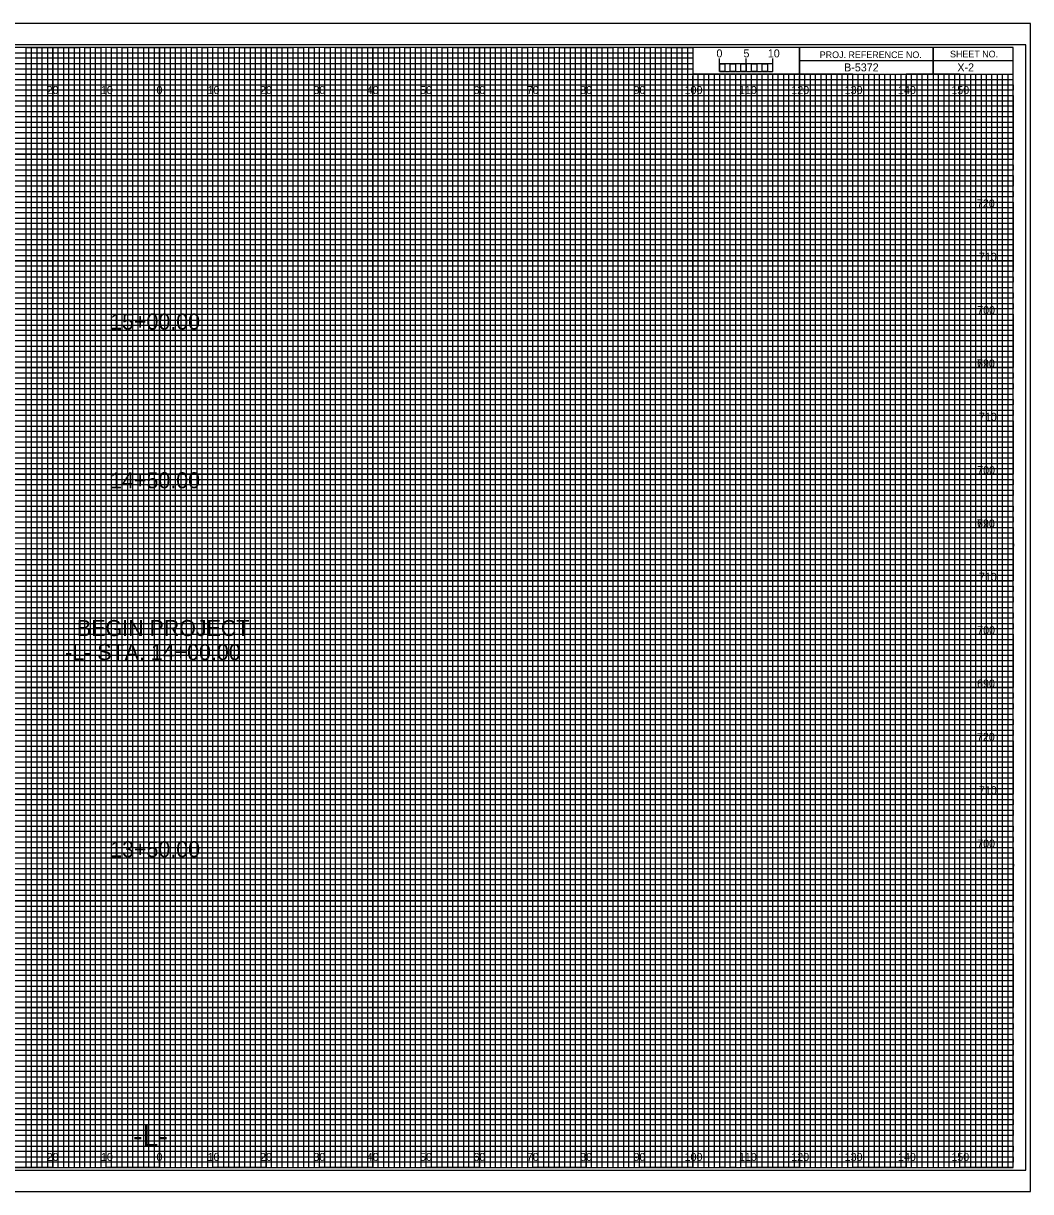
# Model space of a CAD drawing. Extents: x -98 to 717, y -10 to 1974.
# Drawn here: x 134.5 to 323.3, y 215.5 to 434.5 of the extents above; entities that cross this region are included whole.
import ezdxf

# ---------------------------------------------------------------- set-up
doc = ezdxf.new("R2010")
doc.units = 0
for name, color, linetype in [('Exist XS Center Line Elevation Label', 7, 'Continuous'), ('Prop CMT Conc Surface', 7, 'Continuous'), ('Prop CMT Concrete Structures', 7, 'Continuous'), ('Prop CMT Pvmt Course 1', 7, 'Continuous'), ('Prop CMT Pvmt Course 1 CG', 7, 'Continuous'), ('Prop CMT Pvmt Course 2', 7, 'Continuous'), ('Prop CMT Pvmt Course 3', 7, 'Continuous'), ('Prop CMT Pvmt Surface', 7, 'Continuous'), ('Prop CMT Pvmt Surface Shoulder', 7, 'Continuous'), ('Prop CMT Shld Paved Course 1', 7, 'Continuous'), ('Prop CMT Shld Paved Course 2', 7, 'Continuous'), ('Prop CMT Shld Paved Course 3', 7, 'Continuous'), ('Prop CMT Slope Grass', 7, 'Continuous'), ('Prop CMT Subgrade Earthwork', 7, 'Continuous'), ('Prop XS Earthwork Shape', 7, 'Continuous'), ('Prop XS Elevation Labels', 7, 'Continuous'), ('Typical Curb CELL', 7, 'Continuous')]:
    doc.layers.add(name, color=color, linetype=linetype)

msp = doc.modelspace()

# ---------------------------------------------------------------- linework, layer by layer
at = {"layer": 'Exist XS Center Line Elevation Label'}
for p, q in [((0, 429), (260, 429)), ((260, 427.98), (0, 427.98)), ((260, 429), (260, 427.98)), ((0, 427), (260, 427)), ((260, 425.89), (0, 425.89)), ((260, 427), (260, 425.89)), ((0, 424), (320, 424))]:
    msp.add_line(p, q, dxfattribs=at)
for points in [[(0, 423), (270, 423), (320, 423), (320, 422), (0, 422)], [(0, 421), (320, 421), (320, 419), (0, 419)], [(0, 418), (320, 418), (320, 417), (0, 416.98)], [(0, 416), (320, 416), (320, 414), (0, 414)], [(0, 413), (320, 413), (320, 412), (0, 412)], [(0, 411), (320, 411), (320, 409), (0, 409)], [(0, 408), (320, 408), (320, 407), (0, 407)], [(0, 406), (320, 406), (320, 404), (0, 404)], [(0, 403), (320, 403), (320, 402), (0, 402)], [(0, 401), (320, 401), (320, 399), (0, 399)], [(0, 398), (320, 398), (320, 397), (0, 397)], [(0, 396), (320, 396), (320, 393.95), (320, 393), (320, 392), (0, 392)], [(0, 394), (320, 394), (320, 393), (0, 393)], [(0, 391), (320, 391), (320, 389), (0, 389.03)], [(0, 389.03), (320, 389), (320, 388), (0, 388)], [(0, 387), (320, 387), (320, 386), (0, 386)], [(0, 384), (320, 384), (320, 383), (0, 383)], [(0, 382), (320, 382), (320, 381), (0, 381)], [(-0.07, 378.89), (320, 378.89), (320, 377.88), (-0.07, 377.88)], [(0, 377), (320, 377), (320, 376), (0, 376)], [(0, 374), (320, 374), (320, 373), (0, 373)], [(0, 372), (320, 372), (320, 371), (0, 371)], [(0, 369), (320, 369), (320, 368), (0, 368)], [(0, 367), (320, 367), (320, 366), (0, 366)], [(0, 364), (320, 364), (320, 363), (0, 363)], [(0, 362), (320, 362), (320, 361), (0, 361)], [(0, 359), (320, 359), (319.99, 357.98), (0, 358)], [(0, 357), (320, 357), (320, 356), (0, 356)], [(0, 354), (320, 354), (320, 353), (0, 353)], [(0, 352), (320, 352), (320, 351), (0, 351)], [(0, 349), (320, 349), (320, 348), (0, 348)], [(0, 347), (320, 347), (320, 346), (0, 346)], [(0, 344), (320, 344), (320, 343), (0, 343)], [(0, 342), (320, 342), (320, 341), (0, 341)], [(0, 339), (320, 339), (320, 338), (0, 338)], [(0, 336.99), (320.07, 336.91), (320, 336), (0, 336)], [(0, 334), (320, 334), (320, 333), (0, 333)], [(0, 332), (320, 332), (320, 331), (0, 331)], [(0, 329), (320, 329), (320, 328), (0, 328)], [(0, 327), (320, 327), (320, 326), (0, 326)], [(0, 324), (320, 324), (320, 323), (0, 323)], [(0, 322), (320, 322), (320, 321), (0, 321)], [(0, 319), (320, 319), (320, 318), (0, 318)], [(0, 317), (320, 317), (320, 316), (0, 316)], [(0, 314), (320, 314), (320, 313), (0, 313)], [(0, 312), (320, 312), (320, 311), (0, 311)], [(0, 309), (320, 309), (320, 308), (0, 308)], [(0, 307), (320, 307), (320, 306), (0, 306)], [(0, 304), (320, 304), (320, 303), (0, 303)], [(0, 302), (320, 302), (320, 301), (0, 301)], [(0, 299), (320, 299), (319.99, 297.98), (0, 298)], [(0, 297), (320, 297), (320, 296), (0, 296)], [(0, 294), (320, 294), (320, 293), (0, 293)], [(0, 292), (320, 292), (320, 291), (0, 291)], [(0, 289), (320, 289), (320, 288), (0, 288)], [(0, 287), (320, 287), (320, 286), (0, 286)], [(0, 284), (320, 284), (320, 283), (0, 283)], [(0, 282), (320, 282), (320, 281), (0, 281)], [(0, 279), (320, 279), (320, 278), (0, 278)], [(0, 276.99), (320.07, 276.91), (320, 276), (0, 276)], [(0, 274), (320, 274), (320, 273), (0, 273)], [(0, 272), (320, 272), (320, 271), (0, 271)], [(0, 269), (320, 269), (320, 268), (0, 268)], [(0, 267), (320, 267), (320, 266), (0, 266)], [(0, 264), (320, 264), (320, 263), (0, 263)], [(0, 262), (320, 262), (320, 261), (0, 261)], [(0, 259), (320, 259), (320, 258), (0, 258)], [(0, 257), (320, 257), (320, 256), (0, 256)], [(0, 254), (320, 254), (320, 253), (0, 253)], [(0, 252), (320, 252), (320, 251), (0, 251)], [(0, 249), (320, 249), (320, 248), (0, 248)], [(0, 247), (320, 247), (320, 246), (0, 246)], [(0, 244), (320, 244), (320, 243), (0, 243)], [(0, 242), (320, 242), (320, 241), (0, 241)], [(0, 239), (320, 239), (320, 238), (0, 238)], [(0, 237), (320, 237), (320, 236), (0, 236)], [(0, 234), (320, 234), (320, 233), (0, 233)], [(0, 232), (320, 232), (320, 231), (0, 231)], [(0, 229), (320, 229), (320, 228), (0, 228)], [(0, 227), (320, 227), (320, 226), (0, 226)], [(0, 224), (320, 224), (320, 223), (0, 223)], [(0, 222), (320, 222), (320, 221), (0, 221)]]:
    msp.add_lwpolyline(points, dxfattribs=at)
at = {"layer": 'Prop CMT Conc Surface'}
for p, q in [((305, 430), (305, 425)), ((305, 425), (305, 430)), ((280, 427.5), (280, 425)), ((320, 427.49), (280, 427.49)), ((280, 425), (320, 425))]:
    msp.add_line(p, q, dxfattribs=at)
for points in [[(320, 430), (0, 430), (0, 220), (320, 220)], [(280, 430), (260, 430), (260, 425.03), (280, 425.03)], [(320, 430), (280, 430), (280, 425), (320, 425)]]:
    msp.add_lwpolyline(points, close=True, dxfattribs=at)
at = {"layer": 'Prop CMT Concrete Structures'}
for p, q in [((140, 220), (140, 430)), ((150, 220), (150, 430)), ((160, 220), (160, 430)), ((170, 220), (170, 430)), ((180, 220), (180, 430)), ((190, 220), (190, 430)), ((200, 220), (200, 430)), ((210, 220), (210, 430)), ((220, 220), (220, 430)), ((230, 220), (230, 430)), ((240, 220), (240, 430)), ((250, 220), (250, 430)), ((260, 220), (260, 424.69)), ((270, 220), (270, 424.69)), ((280, 220), (280, 424.69)), ((290, 220), (290, 424.69)), ((300, 220), (300, 424.69)), ((310, 220), (310, 424.69)), ((0, 420), (320, 420)), ((0, 410), (320, 410)), ((0, 400), (320, 400)), ((0, 390), (320, 390)), ((0, 380), (320, 380)), ((0, 370), (320, 370)), ((0, 360), (320, 360)), ((0, 350), (320, 350)), ((0, 340), (320, 340)), ((0, 330), (320, 330)), ((0, 320), (320, 320)), ((0, 310), (320, 310)), ((0, 300), (320, 300)), ((0, 290), (320, 290)), ((0, 280), (320, 280)), ((0, 270), (320, 270)), ((0, 260), (320, 260)), ((0, 250), (320, 250)), ((0, 240), (320, 240)), ((0, 230), (320, 230))]:
    msp.add_line(p, q, dxfattribs=at)
at = {"layer": 'Prop CMT Pvmt Course 2'}
msp.add_lwpolyline([(-13.4, 215.5), (323.3, 215.5), (323.3, 434.5), (-13.4, 434.5)], close=True, dxfattribs=at)
at = {"layer": 'Prop CMT Pvmt Course 3'}
msp.add_lwpolyline([(-10.8, 219.5), (322.4, 219.5), (322.4, 430.5), (-10.8, 430.5)], close=True, dxfattribs=at)
at = {"layer": 'Prop CMT Pvmt Surface'}
for p, q in [((323.3, 434.5), (-13.4, 434.5)), ((-13.4, 215.5), (323.3, 215.5))]:
    msp.add_line(p, q, dxfattribs=at)
at = {"layer": 'Prop CMT Slope Grass'}
for p, q in [((265, 425.49), (265, 427.9)), ((265, 426.9), (265, 427.9)), ((270, 425.49), (270, 427.9)), ((275, 425.49), (275, 427.9)), ((275, 426.9), (275, 427.9))]:
    msp.add_line(p, q, dxfattribs=at)
for points in [[(275, 426.9), (265, 426.9), (265, 425.49), (275, 425.49)], [(265, 426.9), (266, 426.9), (266, 425.49), (265, 425.49)], [(267, 426.9), (268, 426.9), (268, 425.49), (267, 425.49)], [(269, 426.9), (270, 426.9), (270, 425.49), (269, 425.49)], [(271, 426.9), (272, 426.9), (272, 425.49), (271, 425.49)], [(273, 426.9), (274, 426.9), (274, 425.49), (273, 425.49)]]:
    msp.add_lwpolyline(points, close=True, dxfattribs=at)
at = {"layer": 'Prop CMT Subgrade Earthwork'}
for p, q in [((267, 425), (266.01, 425)), ((266.01, 425), (266.01, 220)), ((267, 220), (267, 425)), ((269, 425), (268, 425)), ((268, 425), (268, 220)), ((269, 220), (269, 425)), ((266.01, 220), (265, 220)), ((268, 220), (267, 220))]:
    msp.add_line(p, q, dxfattribs=at)
for points in [[(135, 220), (136, 220), (136, 430), (137, 430), (137, 220)], [(137, 220), (138, 220), (138, 430), (139, 430), (139, 220)], [(140, 220), (141, 220), (141, 430), (142, 430), (142, 220)], [(142, 220), (143, 220), (143, 430), (144, 430), (144, 220)], [(145, 220), (146, 220), (146, 430), (147, 430), (147, 220)], [(147, 220), (148, 220), (148, 430), (149, 430), (149, 220)], [(150, 220), (151, 220), (151, 430), (152, 430), (152, 220)], [(152, 220), (153, 220), (153, 430), (154, 430), (154, 220)], [(155, 220), (156, 220), (156, 430), (157, 430), (157, 220)], [(157, 220), (158, 220), (158, 430), (159, 430), (159, 220)], [(160, 220), (161, 220), (161, 430), (162, 430), (162, 220)], [(162, 220), (163, 220), (163, 430), (164, 430), (164, 220)], [(165, 220), (166, 220), (166, 430), (167, 430), (167, 220)], [(167, 220), (168, 220), (168, 430), (169, 430), (169, 220)], [(170, 220), (171, 220), (171, 430), (172, 430), (172, 220)], [(172, 220), (173, 220), (173, 430), (174, 430), (174, 220)], [(175, 220), (176, 220), (176, 430), (177, 430), (177, 220)], [(177, 220), (178, 220), (178, 430), (179, 430), (179, 220)], [(180, 220), (181, 220), (181, 430), (182, 430), (182, 220)], [(182, 220), (183, 220), (183, 430), (184, 430), (184, 220)], [(185, 220), (186, 220), (186, 430), (187, 430), (187, 220)], [(187, 220), (188, 220), (188, 430), (189, 430), (189, 220)], [(190, 220), (191, 220), (191, 430), (192, 430), (192, 220)], [(192, 220), (193, 220), (193, 430), (194, 430), (194, 220)], [(195, 220), (196, 220), (196, 430), (197, 430), (197, 220)], [(197, 220), (198, 220), (198, 430), (199, 430), (199, 220)], [(200, 220), (201, 220), (201, 430), (202, 430), (202, 220)], [(202, 220), (203, 220), (203, 430), (204, 430), (204, 220)], [(205, 220), (206, 220), (206, 430), (207, 430), (207, 220)], [(207, 220), (208, 220), (208, 430), (209, 430), (209, 220)], [(210, 220), (211, 220), (211, 430), (212, 430), (212, 220)], [(212, 220), (213, 220), (213, 430), (214, 430), (214, 220)], [(215, 220), (216, 220), (216, 430), (217, 430), (217, 220)], [(217, 220), (218, 220), (218, 430), (219, 430), (219, 220)], [(220, 220), (221, 220), (221, 430), (222, 430), (222, 220)], [(222, 220), (223, 220), (223, 430), (224, 430), (224, 220)], [(225, 220), (226, 220), (226, 430), (227, 430), (227, 220)], [(227, 220), (228, 220), (228, 430), (229, 430), (229, 220)], [(230, 220), (231, 220), (231, 430), (232, 430), (232, 220)], [(232, 220), (233, 220), (233, 430), (234, 430), (234, 220)], [(235, 220), (236, 220), (236, 430), (237, 430), (237, 220)], [(237, 220), (238, 220), (238, 430), (239, 430), (239, 220)], [(240, 220), (241, 220), (241, 430), (242, 430), (242, 220)], [(242, 220), (243, 220), (243, 430), (244, 430), (244, 220)], [(245, 220), (246, 220), (246, 430), (247, 430), (247, 220)], [(247, 220), (248, 220), (248, 430), (249, 430), (249, 220)], [(250, 220), (251, 220), (251, 430), (252, 430), (252, 220)], [(252, 220), (253, 220), (253, 430), (254, 430), (254, 220)], [(255, 220), (256, 220), (256, 430), (257, 430), (257, 220)], [(257, 220), (258, 220), (258, 430), (259, 430), (259, 220)], [(260, 220), (261, 220), (261, 425), (262.02, 425), (262.02, 220)], [(262, 220), (263, 220), (263, 425), (263.99, 425), (263.99, 220)], [(270, 220), (270.98, 220), (270.98, 425), (272, 425), (272, 220)], [(272, 220), (273, 220), (273, 425), (274.05, 425), (274.05, 220)], [(275, 220), (276, 220), (276, 425), (277, 425), (277, 220)], [(277, 220), (278, 220), (278, 425), (279, 425), (279, 220)], [(280, 220), (281, 220), (281, 425), (282, 425), (282, 220)], [(282, 220), (283, 220), (283, 425), (284, 425), (284, 220)], [(285, 220), (286, 220), (286, 425), (287, 425), (287, 220)], [(287, 220), (288, 220), (288, 425), (289, 425), (289, 220)], [(290, 220), (291, 220), (291, 425), (292, 425), (292, 220)], [(292, 220), (293, 220), (293, 425), (294, 425), (294, 220)], [(295, 220), (296, 220), (296, 425), (297, 425), (297, 220)], [(297, 220), (298, 220), (298, 425), (299, 425), (299, 220)], [(300, 220), (301, 220), (301, 425), (302, 425), (302, 220)], [(302, 220), (303, 220), (303, 425), (304, 425), (304, 220)], [(305, 220), (306, 220), (306, 425), (307, 425), (307, 220)], [(307, 220), (308, 220), (308, 425), (309, 425), (309, 220)], [(310, 220), (311, 220), (311, 425), (312, 425), (312, 220)], [(312, 220), (313, 220), (313, 425), (314, 425), (314, 220)], [(315, 220), (316, 220), (316, 425), (317, 425), (317, 220)], [(317, 220), (318, 220), (318, 425), (319, 425), (319, 220)]]:
    msp.add_lwpolyline(points, dxfattribs=at)
at = {"layer": 'Prop XS Elevation Labels'}
for p, q in [((150, 430), (140, 430)), ((140, 430), (140, 220)), ((150, 220), (150, 430)), ((170, 430), (160, 430)), ((160, 430), (160, 220)), ((170, 220), (170, 430)), ((190, 430), (180, 430)), ((180, 430), (180, 220)), ((190, 220), (190, 430)), ((210, 430), (200, 430)), ((200, 430), (200, 220)), ((210, 220), (210, 430)), ((230, 430), (220, 430)), ((220, 430), (220, 220)), ((230, 220), (230, 430)), ((250, 430), (240, 430)), ((240, 430), (240, 220)), ((250, 220), (250, 430)), ((260, 430), (260, 220)), ((270, 220), (270, 425)), ((290, 425), (280, 425)), ((280, 425), (280, 220)), ((290, 220), (290, 425)), ((310, 425), (300, 425)), ((300, 425), (300, 220)), ((310, 220), (310, 425)), ((140, 220), (130, 220)), ((160, 220), (150, 220)), ((180, 220), (170, 220)), ((200, 220), (190, 220)), ((220, 220), (210, 220)), ((240, 220), (230, 220)), ((260, 220), (250, 220)), ((280, 220), (270, 220)), ((300, 220), (290, 220)), ((320, 220), (310, 220)), ((320, 220), (320, 220))]:
    msp.add_line(p, q, dxfattribs=at)
for points in [[(0, 420), (320, 420), (320, 410), (0, 410)], [(0, 400), (320, 400), (320, 390), (0, 390)], [(0, 380), (320, 380), (320, 370), (0, 370)], [(0, 360), (320, 360), (320, 350), (0, 350)], [(0, 340), (320, 340), (320, 330), (0, 330)], [(0, 320), (320, 320), (320, 310), (0, 310)], [(0, 300), (320, 300), (320, 290), (0, 290)], [(0, 280), (320, 280), (320, 270), (0, 270)], [(0, 260), (320, 260), (320, 250), (0, 250)], [(0, 240), (320, 240), (320, 230), (0, 230)]]:
    msp.add_lwpolyline(points, dxfattribs=at)
at = {"layer": 'Typical Curb CELL'}
for points in [[(125, 220), (135, 220), (135, 430), (145, 430), (145, 220), (155, 220), (155, 430), (165, 430), (165, 220), (175, 220), (175, 430), (185, 430), (185, 220), (195, 220), (195, 430), (205, 430), (205, 220), (215, 220), (215, 430), (225, 430), (225, 220), (235, 220), (235, 430), (245, 430), (245, 220), (255, 220), (255, 430), (259.93, 430), (260, 430), (260, 425), (264.99, 425), (264.99, 220), (275, 220), (275, 425), (285, 425), (285, 220), (295, 220), (295, 425), (305, 425), (305, 220), (315, 220), (315, 425)], [(0, 425), (275, 425)], [(0, 405), (320, 405), (320, 415), (0, 415)], [(0, 385), (320, 385), (320, 395), (0, 395)], [(0, 365), (320, 365), (320, 375), (0, 375)], [(0, 345), (320, 345), (320, 355), (0, 355)], [(0, 325), (320, 325), (320, 335), (0, 335)], [(0, 305), (320, 305), (320, 315), (0, 315)], [(0, 285), (320, 285), (320, 295), (0, 295)], [(0, 265), (320, 265), (320, 275), (0, 275)], [(0, 245), (320, 245), (320, 255), (0, 255)], [(0, 225), (320, 225), (320, 235), (0, 235)]]:
    msp.add_lwpolyline(points, dxfattribs=at)

# ---------------------------------------------------------------- texts
at = {"layer": 'Prop CMT Conc Surface'}
for s, p in [('PROJ. REFERENCE NO.', (283.77, 427.99)), ('SHEET NO.', (308.19, 428.12))]:
    msp.add_text(s, height=1.25, dxfattribs=at).set_placement(p)
at = {"layer": 'Prop CMT Pvmt Course 1'}
for s, p in [('15+00.00', (150.77, 377.1)), ('14+50.00', (150.77, 347.35)), ('BEGIN PROJECT', (144.55, 319.65)), ('-L- STA. 14+00.00', (142.34, 315.15)), ('13+50.00', (150.77, 278.19))]:
    msp.add_text(s, height=3, dxfattribs=at).set_placement(p)
at = {"layer": 'Prop CMT Pvmt Course 1 CG'}
for s, p in [('720', (313.23, 400)), ('710', (313.61, 390)), ('700', (313.28, 380)), ('720', (313.23, 370)), ('690', (313.26, 370)), ('710', (313.61, 360)), ('700', (313.28, 350)), ('720', (313.23, 340)), ('690', (313.26, 340)), ('710', (313.61, 330)), ('700', (313.28, 320)), ('690', (313.26, 310)), ('720', (313.23, 300)), ('710', (313.61, 290)), ('700', (313.28, 280))]:
    msp.add_text(s, height=1.5, dxfattribs=at).set_placement(p)
at = {"layer": 'Prop CMT Pvmt Surface Shoulder'}
for s, p in [('5', (269.47, 428.12)), ('10', (274.04, 428.12))]:
    msp.add_text(s, height=1.5, dxfattribs=at).set_placement(p)
at = {"layer": 'Prop CMT Shld Paved Course 1'}
msp.add_text('X-2', height=1.5, dxfattribs=at).set_placement((309.57, 425.5))
at = {"layer": 'Prop CMT Shld Paved Course 2'}
msp.add_text('B-5372', height=1.5, dxfattribs=at).set_placement((288.34, 425.5))
at = {"layer": 'Prop CMT Shld Paved Course 3'}
msp.add_text('-L-', height=4, dxfattribs=at).set_placement((155.06, 224))
at = {"layer": 'Prop CMT Slope Grass'}
msp.add_text('0', height=1.5, dxfattribs=at).set_placement((264.41, 428.12))
at = {"layer": 'Prop XS Earthwork Shape'}
for s, p in [('20', (138.86, 421.25)), ('10', (149.04, 421.25)), ('0', (159.45, 421.25)), ('0', (159.45, 421.25)), ('10', (169.04, 421.25)), ('20', (178.86, 421.25)), ('30', (188.86, 421.25)), ('40', (198.86, 421.25)), ('50', (208.86, 421.25)), ('60', (218.86, 421.25)), ('70', (228.86, 421.25)), ('80', (238.86, 421.25)), ('90', (248.86, 421.25)), ('100', (258.44, 421.25)), ('110', (268.62, 421.25)), ('120', (278.44, 421.25)), ('130', (288.44, 421.25)), ('140', (298.44, 421.25)), ('150', (308.44, 421.25)), ('20', (138.86, 221.25)), ('10', (149.04, 221.25)), ('0', (159.45, 221.25)), ('0', (159.45, 221.25)), ('10', (169.04, 221.25)), ('20', (178.86, 221.25)), ('30', (188.86, 221.25)), ('40', (198.86, 221.25)), ('50', (208.86, 221.25)), ('60', (218.86, 221.25)), ('70', (228.86, 221.25)), ('80', (238.86, 221.25)), ('90', (248.86, 221.25)), ('100', (258.44, 221.25)), ('110', (268.62, 221.25)), ('120', (278.44, 221.25)), ('130', (288.44, 221.25)), ('140', (298.44, 221.25)), ('150', (308.44, 221.25))]:
    msp.add_text(s, height=1.5, dxfattribs=at).set_placement(p)

doc.saveas('drawing.dxf')
